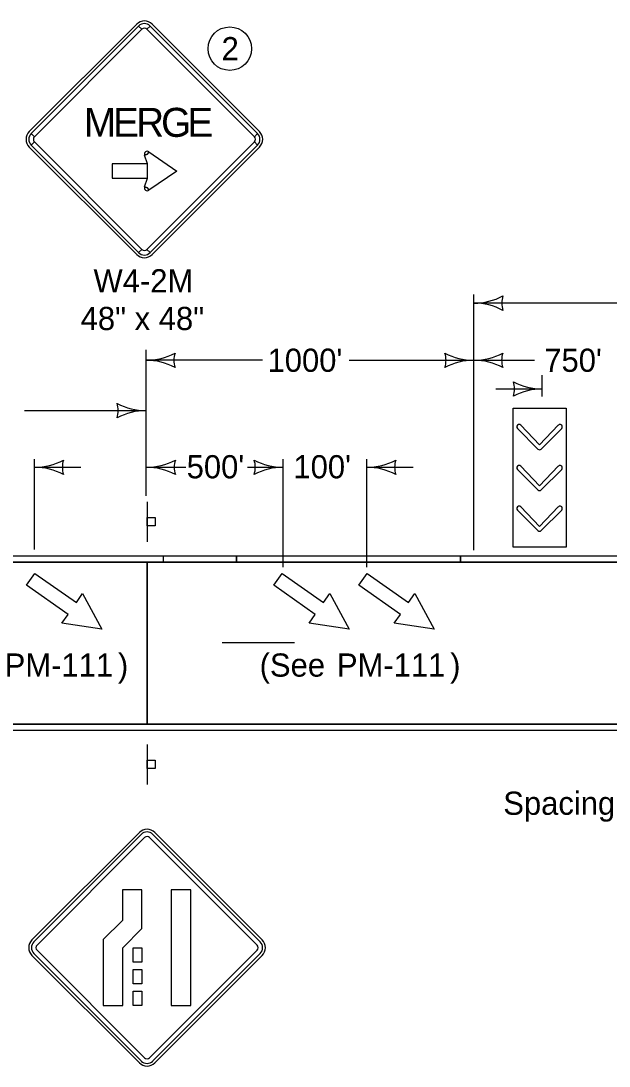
# Model space of a CAD drawing. Extents: x 10124 to 16850, y 7924 to 12166.
# Drawn here: x 10892 to 11298, y 9011 to 9733 of the extents above; entities that cross this region are included whole.
import ezdxf

# ---------------------------------------------------------------- set-up
doc = ezdxf.new("R2010")
doc.units = 0
for name, color, linetype in [('dsnShtPlotShapeBatchPrint', 7, 'Continuous'), ('dsnStdLabel', 7, 'Continuous'), ('dsnStdLineWork', 7, 'Continuous'), ('dsnStdShading', 7, 'Continuous'), ('SheetText', 7, 'Continuous')]:
    doc.layers.add(name, color=color, linetype=linetype)

msp = doc.modelspace()

# ---------------------------------------------------------------- linework, layer by layer
at = {"layer": 'dsnShtPlotShapeBatchPrint'}
msp.add_circle((11035.84, 9713.4), 15, dxfattribs=at)
at = {"layer": 'dsnStdLabel'}
for p, q in [((10971.58, 9730.38), (10897.33, 9656.13)), ((10972.9, 9729.05), (10975.11, 9726.84)), ((10978.65, 9726.84), (10980.86, 9729.05)), ((11056.43, 9656.13), (10982.18, 9730.38)), ((10900.86, 9652.59), (10898.66, 9654.8)), ((11055.1, 9654.8), (11052.89, 9652.59)), ((10898.66, 9646.85), (10900.86, 9649.06)), ((11052.89, 9649.06), (11055.1, 9646.85)), ((10897.33, 9645.52), (10971.58, 9571.28)), ((10978.91, 9640.51), (10976.98, 9639.87)), ((10980, 9642.23), (10978.91, 9640.51)), ((10982.18, 9571.28), (11056.43, 9645.52)), ((10976.98, 9618.04), (10978.91, 9617.39)), ((10978.91, 9617.39), (10980, 9615.67)), ((10975.11, 9574.81), (10972.9, 9572.6)), ((10980.86, 9572.6), (10978.65, 9574.81)), ((11251.13, 9437.05), (11265.23, 9451.15)), ((11251.13, 9408.82), (11265.23, 9422.91)), ((11251.13, 9380.75), (11265.23, 9394.85)), ((10978.7, 9233.04), (10978.7, 9205.54)), ((10973.39, 9172.37), (10899.14, 9098.12)), ((10899.15, 9098.12), (10973.39, 9172.37)), ((10900.47, 9096.8), (10974.72, 9171.04)), ((10973.39, 9172.37), (10973.39, 9172.37)), ((10982.67, 9171.04), (11056.92, 9096.8)), ((10984, 9172.37), (11058.25, 9098.12)), ((11058.25, 9098.12), (10984, 9172.37)), ((10976.93, 9168.83), (10902.68, 9094.59)), ((10976.93, 9168.83), (10976.93, 9168.84)), ((11054.71, 9094.59), (10980.46, 9168.83)), ((10902.68, 9091.05), (10976.93, 9016.81)), ((10980.46, 9016.81), (11054.71, 9091.05)), ((10899.14, 9087.52), (10973.39, 9013.27)), ((10973.39, 9013.27), (10899.15, 9087.52)), ((10974.72, 9014.6), (10900.47, 9088.84)), ((11056.92, 9088.84), (10982.67, 9014.6)), ((11058.25, 9087.52), (10984, 9013.27)), ((10984, 9013.27), (11058.25, 9087.52))]:
    msp.add_line(p, q, dxfattribs=at)
for points in [[(10972.9, 9729.05), (10898.66, 9654.8), (10900.86, 9652.59), (10975.11, 9726.84), (10972.9, 9729.05)], [(11055.1, 9654.8), (10980.86, 9729.05), (10978.65, 9726.84), (11052.89, 9652.59), (11055.1, 9654.8)], [(10898.66, 9646.85), (10972.9, 9572.6), (10975.11, 9574.81), (10900.86, 9649.06), (10898.66, 9646.85)], [(10980.86, 9572.6), (11055.1, 9646.85), (11052.89, 9649.06), (10978.65, 9574.81), (10980.86, 9572.6)], [(10999.22, 9628.95), (10980, 9615.67), (10978.91, 9617.39), (10976.98, 9618.04), (10978.97, 9623.95), (10978.97, 9633.95), (10976.98, 9639.87), (10978.91, 9640.51), (10980, 9642.23), (10999.22, 9628.95)], [(10954.53, 9633.95), (10954.53, 9623.95), (10978.97, 9623.95), (10978.97, 9633.95), (10954.53, 9633.95)], [(11268.3, 9465.2), (11268.3, 9369.2), (11231.6, 9369.2), (11231.6, 9465.2)], [(10978.79, 9216.59), (10978.79, 9222.22), (10984.42, 9222.22), (10984.42, 9216.59)], [(10961.7, 9111.67), (10948.44, 9098.41), (10948.44, 9052.82), (10961.94, 9052.82), (10961.94, 9092.82), (10975.2, 9106.07), (10975.2, 9132.82), (10961.7, 9132.82)], [(10995.45, 9132.82), (10995.45, 9052.82), (11008.95, 9052.82), (11008.95, 9132.82)], [(10969.2, 9092.82), (10975.2, 9092.82), (10975.2, 9082.82), (10969.2, 9082.82)], [(10969.2, 9077.82), (10975.2, 9077.82), (10975.2, 9067.82), (10969.2, 9067.82)], [(10969.2, 9062.82), (10975.2, 9062.82), (10975.2, 9052.82), (10969.2, 9052.82)]]:
    msp.add_lwpolyline(points, close=True, dxfattribs=at)
for points in [[(11262.9, 9453.48), (11262.84, 9453.42), (11249.95, 9439.85), (11237.04, 9453.43)], [(11234.64, 9451.18), (11234.69, 9451.13), (11248.78, 9437.04), (11248.79, 9437.03)], [(11234.64, 9422.94), (11234.69, 9422.89), (11248.78, 9408.81), (11248.79, 9408.79)], [(11262.9, 9425.25), (11262.84, 9425.18), (11249.95, 9411.61), (11237.04, 9425.2)], [(11234.64, 9394.88), (11234.69, 9394.83), (11248.78, 9380.74), (11248.79, 9380.73)], [(11262.9, 9397.19), (11262.84, 9397.12), (11249.95, 9383.55), (11237.04, 9397.13)], [(10974.72, 9171.04), (10900.47, 9096.8)], [(11056.92, 9096.8), (10982.67, 9171.04)], [(10976.93, 9168.84), (10902.68, 9094.59)], [(11054.71, 9094.59), (10980.46, 9168.84)], [(10902.68, 9091.05), (10976.93, 9016.81)], [(10980.46, 9016.81), (11054.71, 9091.05)], [(10900.47, 9088.84), (10974.72, 9014.6)], [(10982.67, 9014.6), (11056.92, 9088.84)]]:
    msp.add_lwpolyline(points, dxfattribs=at)
for centre, radius, start, end in [((10976.88, 9725.07), 7.5, 44.99999, 134.99974), ((10976.88, 9725.07), 5.62, 44.99999, 134.99974), ((10976.88, 9725.07), 2.5, 44.99999, 134.99974), ((10902.63, 9650.83), 7.5, 134.99974, 224.99995), ((10902.63, 9650.83), 5.62, 134.99974, 224.99995), ((11051.12, 9650.83), 5.62, 315.00016, 44.9998), ((11051.12, 9650.83), 7.5, 315.00016, 44.9998), ((10902.63, 9650.83), 2.5, 134.99974, 224.99995), ((11051.12, 9650.83), 2.5, 315.00016, 44.9998), ((10978.91, 9640.51), 2.03, 57.68757, 198.58133), ((10978.91, 9617.39), 2.03, 161.41814, 302.31247), ((10976.88, 9576.58), 2.5, 224.99995, 315.00016), ((10976.88, 9576.58), 7.5, 224.99995, 315.00016), ((10976.88, 9576.58), 5.62, 224.99995, 315.00016), ((11235.83, 9452.32), 1.65, 42.63982, 223.799), ((11264.07, 9452.32), 1.65, 314.71897, 134.90254), ((11249.95, 9438.2), 1.65, 225.39017, 315.83844), ((11235.83, 9424.08), 1.65, 42.63982, 223.799), ((11264.07, 9424.08), 1.65, 314.71897, 134.90254), ((11249.95, 9409.97), 1.65, 225.39017, 315.83844), ((11235.83, 9396.02), 1.65, 42.63982, 223.799), ((11264.07, 9396.02), 1.65, 314.71897, 134.90254), ((11249.95, 9381.9), 1.65, 225.39017, 315.83844), ((10978.7, 9167.07), 7.5, 45.00026, 135.00001), ((10978.7, 9167.07), 7.5, 45.00026, 135.00001), ((10978.7, 9167.07), 5.63, 45.00026, 135.00001), ((10978.7, 9167.07), 5.63, 45.00026, 135.00001), ((10978.7, 9167.07), 2.5, 45.00026, 135.00001), ((10978.7, 9167.07), 2.5, 45.00026, 135.00001), ((10904.45, 9092.82), 7.5, 135.0002, 224.99984), ((10904.45, 9092.82), 7.5, 135.0002, 224.99984), ((11052.94, 9092.82), 7.5, 315.00005, 45.00026), ((11052.94, 9092.82), 7.5, 315.00005, 45.00026), ((10904.45, 9092.82), 5.63, 135.0002, 224.99984), ((10904.45, 9092.82), 5.63, 135.0002, 224.99984), ((10904.45, 9092.82), 2.5, 135.0002, 224.99984), ((10904.45, 9092.82), 2.5, 135.0002, 224.99984), ((11052.94, 9092.82), 2.5, 315.00005, 45.00026), ((11052.94, 9092.82), 2.5, 315.00005, 45.00026), ((11052.94, 9092.82), 5.63, 315.00005, 45.00026), ((11052.94, 9092.82), 5.63, 315.00005, 45.00026), ((10978.7, 9018.57), 7.5, 224.99984, 315.00005), ((10978.7, 9018.57), 7.5, 224.99984, 315.00005), ((10978.7, 9018.57), 5.63, 224.99984, 315.00005), ((10978.7, 9018.57), 5.63, 224.99984, 315.00005), ((10978.7, 9018.57), 2.5, 224.99984, 315.00005), ((10978.7, 9018.57), 2.5, 224.99984, 315.00005)]:
    msp.add_arc(centre, radius, start, end, dxfattribs=at)
at = {"layer": 'dsnStdLineWork'}
for p, q in [((10151.91, 9359.04), (11348.15, 9359.04)), ((10895.49, 9342.96), (10901.22, 9351.16)), ((10901.22, 9351.16), (10929.89, 9331.09)), ((11066.3, 9342.96), (11072.03, 9351.16)), ((11072.03, 9351.16), (11100.7, 9331.09)), ((11125.06, 9342.96), (11130.8, 9351.16)), ((11130.8, 9351.16), (11159.47, 9331.09)), ((10924.15, 9322.89), (10895.49, 9342.96)), ((10929.89, 9331.09), (10934.19, 9337.23)), ((10934.19, 9337.23), (10947.5, 9312.65)), ((11094.96, 9322.89), (11066.3, 9342.96)), ((11100.7, 9331.09), (11105, 9337.23)), ((11105, 9337.23), (11118.31, 9312.65)), ((11153.73, 9322.89), (11125.06, 9342.96)), ((11159.47, 9331.09), (11163.77, 9337.23)), ((11163.77, 9337.23), (11177.07, 9312.65)), ((10919.85, 9316.75), (10924.15, 9322.89)), ((11090.66, 9316.75), (11094.96, 9322.89)), ((11149.43, 9316.75), (11153.73, 9322.89)), ((10947.5, 9312.65), (10919.85, 9316.75)), ((11118.31, 9312.65), (11090.66, 9316.75)), ((11177.07, 9312.65), (11149.43, 9316.75)), ((10143.95, 9247.02), (11762.1, 9247.02))]:
    msp.add_line(p, q, dxfattribs=at)
msp.add_lwpolyline([(11030.64, 9303.44), (11080.63, 9303.44)], dxfattribs=at)
at = {"layer": 'dsnStdShading'}
for p, q in [((11072.72, 9363.04), (10880.75, 9363.04)), ((10880.75, 9359.04), (11072.72, 9359.04)), ((10978.7, 9247.04), (10978.7, 9359.04)), ((11040.56, 9359.04), (10978.7, 9359.04)), ((10978.7, 9359.04), (10978.7, 9247.04)), ((11040.56, 9363.04), (10989.74, 9363.04)), ((10989.74, 9363.04), (10989.74, 9359.04)), ((10989.74, 9359.04), (11040.56, 9359.04)), ((11195.19, 9363.04), (11040.56, 9363.04)), ((11040.56, 9363.04), (11040.56, 9359.04)), ((11040.56, 9359.04), (11040.56, 9363.04)), ((11040.56, 9359.04), (11195.19, 9359.04)), ((11195.19, 9359.04), (11040.56, 9359.04)), ((11072.72, 9359.04), (11072.72, 9363.04)), ((11195.19, 9359.04), (11195.19, 9363.04)), ((12409.55, 9363.04), (11195.19, 9363.04)), ((11195.19, 9363.04), (11195.19, 9359.04)), ((11406.55, 9359.04), (11195.19, 9359.04)), ((11195.19, 9359.04), (11406.55, 9359.04)), ((11527.46, 9247.04), (10143.93, 9247.04)), ((10143.93, 9247.04), (10978.7, 9247.04)), ((10147.93, 9243.04), (11554.23, 9243.04)), ((10147.93, 9243.04), (11525.74, 9243.04)), ((10978.7, 9247.04), (11527.46, 9247.04))]:
    msp.add_line(p, q, dxfattribs=at)
msp.add_lwpolyline([(10978.7, 9359.04), (10880.75, 9359.04), (10829.93, 9359.04)], dxfattribs=at)
msp.add_lwpolyline([(11040.56, 9359.04), (11195.19, 9359.04), (11195.19, 9363.04), (11040.56, 9363.04)], close=True, dxfattribs=at)
at = {"layer": 'SheetText'}
for p, q in [((11204.53, 9367.17), (11204.53, 9543.8)), ((11681.53, 9537.75), (11204.59, 9537.75)), ((10978.04, 9404.81), (10978.04, 9505.45)), ((11058.53, 9498.32), (10978.04, 9498.32)), ((11118.34, 9498.32), (11204.53, 9498.32)), ((11204.53, 9498.32), (11246.5, 9498.32)), ((11251.83, 9473.2), (11251.83, 9488.06)), ((11219.83, 9478.51), (11251.83, 9478.51)), ((10894.06, 9463.58), (10978.04, 9463.58)), ((10900.96, 9367.57), (10900.96, 9430.02)), ((11072.72, 9355.42), (11072.72, 9430.02)), ((11130.54, 9355.42), (11130.54, 9430.02)), ((10900.96, 9424.43), (10932.96, 9424.43)), ((10978.85, 9424.43), (11005.47, 9424.43)), ((11048.22, 9424.43), (11072.72, 9424.43)), ((11130.54, 9424.43), (11162.54, 9424.43)), ((10978.7, 9400.54), (10978.7, 9373.04))]:
    msp.add_line(p, q, dxfattribs=at)
msp.add_lwpolyline([(10978.79, 9384.09), (10978.79, 9389.72), (10984.42, 9389.72), (10984.42, 9384.09)], close=True, dxfattribs=at)
for centre, radius, start, end in [((11204.59, 9580.25), 42.5, 270, 298.07249), ((11240.23, 9537.75), 16.42, 162.26665, 197.73335), ((11204.59, 9495.25), 42.5, 61.92751, 90), ((10978.04, 9540.82), 42.5, 270, 298.07249), ((11013.67, 9498.32), 16.42, 162.26665, 197.73335), ((11168.89, 9498.32), 16.42, 342.26665, 17.73335), ((11204.53, 9540.82), 42.5, 241.92751, 270), ((11204.53, 9540.82), 42.5, 270, 298.07249), ((11240.16, 9498.32), 16.42, 162.26665, 197.73335), ((10978.04, 9455.82), 42.5, 61.92751, 90), ((11204.53, 9455.82), 42.5, 90, 118.07249), ((11204.53, 9455.82), 42.5, 61.92751, 90), ((11216.2, 9478.51), 16.42, 342.26665, 17.73335), ((11251.83, 9521.01), 42.5, 241.92751, 270), ((11251.83, 9436.01), 42.5, 90, 118.07249), ((10942.4, 9463.58), 16.42, 342.26665, 17.73335), ((10978.04, 9506.08), 42.5, 241.92751, 270), ((10978.04, 9421.08), 42.5, 90, 118.07249), ((10900.96, 9466.93), 42.5, 270, 298.07249), ((10900.96, 9381.93), 42.5, 61.92751, 90), ((10936.6, 9424.43), 16.42, 162.26665, 197.73335), ((10978.25, 9466.93), 42.5, 270, 298.07249), ((10978.25, 9381.93), 42.5, 61.92751, 90), ((11013.89, 9424.43), 16.42, 162.26665, 197.73335), ((11037.08, 9424.43), 16.42, 342.26665, 17.73335), ((11072.72, 9466.93), 42.5, 241.92751, 270), ((11072.72, 9381.93), 42.5, 90, 118.07249), ((11130.54, 9466.93), 42.5, 270, 298.07249), ((11130.54, 9381.93), 42.5, 61.92751, 90), ((11166.18, 9424.43), 16.42, 162.26665, 197.73335)]:
    msp.add_arc(centre, radius, start, end, dxfattribs=at)

# ---------------------------------------------------------------- texts
at = {"layer": 'dsnShtPlotShapeBatchPrint'}
msp.add_text('2', height=16, dxfattribs=at).set_placement((11030.22, 9705.4))
at = {"layer": 'dsnStdLabel'}
for s, p in [('M', (10935, 9652.55)), ('E', (10955.2, 9652.55)), ('R', (10971.18, 9652.55)), ('G', (10988.4, 9652.55)), ('E', (11006.57, 9652.55))]:
    msp.add_text(s, height=20, dxfattribs=at).set_placement(p)
at = {"layer": 'SheetText'}
for s, p in [('W4-2M', (10941.71, 9545.16)), ('48" x 48"', (10932.81, 9519.16)), ("1000'", (11061.97, 9490.32)), ("750'", (11253.19, 9490.32)), ("500'", (11006.08, 9416.8)), ("100'", (11079.85, 9416.8)), ('PM-111', (10880.33, 9279.91)), (')', (10958.59, 9279.91)), ('(See ', (11056.5, 9279.91)), ('PM-111', (11109.91, 9279.91)), (')', (11188.17, 9279.91)), ("Spacing = 65'", (11224.86, 9184.53))]:
    msp.add_text(s, height=16, dxfattribs=at).set_placement(p)

doc.saveas('drawing.dxf')
